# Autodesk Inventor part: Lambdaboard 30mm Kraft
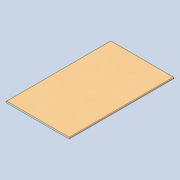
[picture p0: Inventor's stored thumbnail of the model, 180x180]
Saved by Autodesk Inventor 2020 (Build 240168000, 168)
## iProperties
Created: 2020-11
Part Number: Lambdaboard 30mm Kraft
Material: Generic
Document SubType Name: Modeling
Designer: Yolande
Density: 1 g/cm^3
Appearance: Default
Author: Yolande
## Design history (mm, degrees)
sketch "Sketch1"
  geometry: L1 (10, 0)-(1210, 0); L2 (1220, 10)-(1220, 20); L3 (1210, 30)-(10, 30); L4 (0, 20)-(0, 10); A1 r 10 centre (10, 20) between (10, 30) and (0, 20); A2 r 10 centre (10, 10) between (0, 10) and (10, 0); A3 r 10 centre (1210, 20) between (1220, 20) and (1210, 30); A4 r 10 centre (1210, 10) between (1210, 0) and (1220, 10); 3 further points
  constraints: 8 end point, 8 point on circle, 8 tangent, 6 point on line, 4 centre point, 3 equal radius, 3 perpendicular, 1 horizontal
  dimensions: "d0" = 1220 distance of point (0, 0) point (1220, 0); "d1" = 30 distance of point (1220, 0) point (1220, 30); "d2" = 10 radius of A1
extrude "Extrusion1" new body sketch "Sketch1" distance "d3" = 2000; taper "d4" = 0 deg
body "Solid1"
